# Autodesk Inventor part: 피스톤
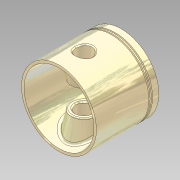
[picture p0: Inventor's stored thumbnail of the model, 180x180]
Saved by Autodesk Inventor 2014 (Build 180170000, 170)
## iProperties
Manager: KYOUNG IL JANG
Company: 한국ATC센터
Created: 2012-10
Part Number: 피스톤
Document SubType Name: Modeling
Density: 1 g/cm^3
Checked By: KYOUNG IL JANG
Vendor: CBT Solutions
Designer: KYOUNG IL JANG
Material: 일반
Appearance: _시험_금속-티타늄(광택)
Author: KYOUNG IL JANG
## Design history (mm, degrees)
sketch "스케치1"
  geometry: L1 (0, 0)-(0, 50); L2 (0, 50)-(30, 50); L3 (30, 50)-(30, 45); L4 (30, 45)-(28, 45); L5 (28, 45)-(28, 44); L6 (28, 44)-(30, 44); L7 (30, 44)-(30, 43); L8 (30, 43)-(28, 43); L9 (28, 43)-(28, 42); L10 (28, 42)-(30, 42); L11 (30, 42)-(30, 0); L12 (30, 0)-(28, 0); L13 (28, 0)-(23, 45); L14 (23, 45)-(0, 45)
  constraints: 28 end point, 10 parallel, 5 collinear, 2 perpendicular, 2 point on line, 1 vertical
  dimensions: "d0" = 50 distance of L1.start L1.end; "d1" = 60 diameter of L3 L1; "d2" = 5 distance between parallel lines of L2 L14; "d3" = 2 distance of L11.end L12.end; "d5" = 5 distance of L2.end L3.end; "d6" = 1 distance of L4.end L5.end; "d7" = 2 distance of L9.end L10.end; "d26" = 46 diameter of L13.end L1
revolve "회전1" sketch "스케치1" stored, may be unused: angle "d8" = 90 deg
node "작업 평면1"
sketch "스케치2"
  geometry: L1 (-28, 0)-(28, 0) reference; C1 r 10 at (0, 20); C2 r 6.5 at (0, 20); 1 further point
  constraints: 2 centre point, 1 coincident, 1 vertical alignment
  dimensions: "d10" = 20 diameter of C1; "d13" = 20 distance from line of C1.centre L1; "d14" = 13 diameter of C2
extrude "돌출1" join sketch "스케치2" stored distance "d11" = 10; taper "d12" = 12 deg
extrude "돌출2" cut sketch "스케치2" stored distance "d15" = 10; taper "d16" = 0 deg
fillet "모깎기1" dims "d17" = 2, "d21" = 3
chamfer "모따기1" distance "d18" = 1; stored, may be unused: second distance "d19" = 2, angle "d20" = 45 deg
chamfer "모따기2" distance "d22" = 1; stored, may be unused: second distance "d23" = 2, angle "d24" = 45 deg
fillet "모깎기2" dims "d25" = 1
node "솔리드1"
mirror "대칭1"
